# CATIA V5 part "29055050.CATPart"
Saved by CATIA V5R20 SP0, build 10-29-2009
Part number: 29055050
Definition: NONE
Nomenclature: 29055050
Source: Unknown
Description: 29055050
Bounding box of the stored display mesh (mm): x -25 to 44.548, y -41.5 to 76.048, z -31.5 to 31.5
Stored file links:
  C:\Users\Utente\Desktop\IO LAVORO\3D X SITO CF\X SITO\PLASTICA\RF1\29055050.CATPart
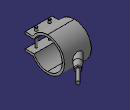
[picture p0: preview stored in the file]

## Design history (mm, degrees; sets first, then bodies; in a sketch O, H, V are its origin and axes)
Body1 "29055050" (main body)
  Solid1: solid without history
